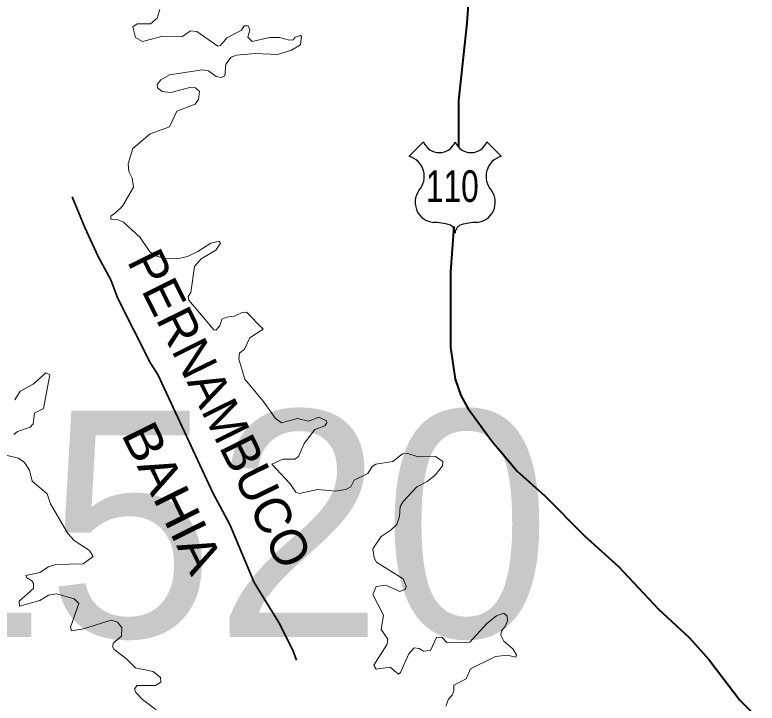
# Model space of a CAD drawing. Extents: x 553962 to 842807, y 8883888 to 9032388.
# Drawn here: x 579374 to 581014, y 8914801 to 8916321 of the extents above; entities that cross this region are included whole.
import ezdxf
from ezdxf.enums import TextEntityAlignment as Align

# ---------------------------------------------------------------- set-up
doc = ezdxf.new("R2010")
doc.units = 0
doc.header["$LTSCALE"] = 200
doc.linetypes.add('LONG_DASH_SHORT_DASH', pattern=[9.9, 6, -1.2, 1.5, -1.2])
doc.layers.add('6', color=7, linetype='Continuous', lineweight=13)

msp = doc.modelspace()

# ---------------------------------------------------------------- linework, layer by layer
at = {"layer": '6', "lineweight": 25}
for p, q in [((580244.9, 8916008.7), (580276.8, 8916040.7)), ((580416.7, 8916040.7), (580448.7, 8916008.7))]:
    msp.add_line(p, q, dxfattribs=at)
at = {"layer": '6', "lineweight": 40}
for points in [[(579213.9, 8917803.6), (579228.4, 8917763.4), (579242.2, 8917742.7), (579298.8, 8917690.5), (579364.6, 8917617.7), (579396.1, 8917591.3), (579545.7, 8917448.6), (579623.5, 8917387.3), (579718.5, 8917299.9), (579761.2, 8917250.1), (579934.8, 8917073.4), (579974.1, 8917041), (580094.4, 8916919), (580138.8, 8916860.8), (580185.2, 8916812.2), (580237.9, 8916747.8), (580356.4, 8916554.1), (580378.4, 8916492), (580386.2, 8916445.1), (580380.2, 8916408), (580372.4, 8916302.5), (580354.2, 8916132.1), (580354.2, 8916028.7)], [(580343.7, 8915853.7), (580336.1, 8915753.4), (580336.5, 8915587.3), (580346.4, 8915516.3), (580359, 8915480.1), (580374.6, 8915452.4), (580426, 8915381.5), (580483.5, 8915313.2), (580544.8, 8915258.9), (580632.4, 8915170.4), (580707.5, 8915102.2), (580796.1, 8915008), (580864.8, 8914944.9), (580908, 8914896.5), (580975.6, 8914807.3), (581014.1, 8914768.8)]]:
    msp.add_lwpolyline(points, dxfattribs=at)
at = {"layer": '6'}
for points in [[(580007.4, 8916273.3), (580005, 8916275.8), (579993.4, 8916271.9), (579988.7, 8916266.2), (579980.8, 8916265), (579958.6, 8916271.3), (579936.5, 8916271.3), (579898.3, 8916262), (579888.5, 8916271.8), (579893.2, 8916288), (579889.2, 8916296.8), (579880.4, 8916297.2), (579874.8, 8916287), (579841.8, 8916270.1), (579827.8, 8916253.1), (579822.2, 8916252.2), (579776.1, 8916284.1), (579776.1, 8916284.1), (579761.9, 8916285.8), (579744.5, 8916273.1), (579700.5, 8916273.9), (579656.1, 8916262.4), (579640, 8916271.3), (579634.5, 8916294.7), (579643.7, 8916301.5), (579673.1, 8916301.5), (579688.3, 8916313.8), (579694.3, 8916332.9)], [(579827, 8915819.2), (579826.3, 8915820.9), (579806.9, 8915817.1), (579778.4, 8915798), (579755.5, 8915787), (579732.5, 8915781.9), (579702, 8915783.2), (579689.3, 8915787), (579671.8, 8915797.6), (579650.6, 8915829.1), (579613.6, 8915863), (579601.7, 8915868.1), (579586, 8915869.9), (579586, 8915876.6), (579597.1, 8915884.3), (579611.5, 8915898.7), (579635.7, 8915940.4), (579632.8, 8915960), (579625.5, 8915975.2), (579623.8, 8915992.2), (579634.5, 8916026.2), (579673, 8916058.4), (579715.6, 8916073.8), (579731.3, 8916108.2), (579772.1, 8916123.5), (579779.7, 8916134.4), (579781.8, 8916151.9), (579772.9, 8916160), (579760.6, 8916160.9), (579718.1, 8916149.8), (579699.4, 8916151.6), (579689.2, 8916160), (579688, 8916167.1), (579696, 8916177.8), (579715.7, 8916188.6), (579788.6, 8916199.5), (579801.3, 8916197.8), (579818.4, 8916184.7), (579830.3, 8916182.6), (579837.5, 8916186.4), (579840.1, 8916212.3), (579852, 8916228), (579863.6, 8916232.3), (579905.1, 8916236.1), (579954.3, 8916233.9), (579985, 8916242.9), (580004.9, 8916254.8), (580007.4, 8916273.3)], [(579921.2, 8915628.2), (579885.3, 8915664.2), (579876.2, 8915663.8), (579859.2, 8915655.3), (579842.2, 8915653.6), (579830.8, 8915648.5), (579826.8, 8915634.3), (579817.6, 8915624.4), (579813.3, 8915625.1), (579758.5, 8915690.5), (579756.4, 8915699.1), (579762.7, 8915707.9), (579770.8, 8915765.3), (579785.7, 8915781.9), (579817.5, 8915801), (579828.2, 8915816.6), (579827, 8915819.2)], [(580319.7, 8915333.8), (580319.7, 8915334.1), (580303.4, 8915345.2), (580265, 8915344.8), (580242.4, 8915351.9), (580230.5, 8915351.1), (580209.3, 8915334.1), (580171.4, 8915328.2), (580163.5, 8915323.6), (580153.6, 8915308.2), (580123.4, 8915293.3), (580116.2, 8915278.5), (580104.8, 8915272.5), (580081.8, 8915268.7), (580043.5, 8915272.5), (580002, 8915263.6), (579994.3, 8915267), (579994.3, 8915267), (579982.4, 8915285.2), (579941.6, 8915328.6), (579966.2, 8915339.6), (579992.4, 8915339.6), (580000.2, 8915345.2), (580013.4, 8915374.5), (580036.8, 8915405.1), (580058.9, 8915413.2), (580063.1, 8915419.8), (580062.2, 8915424.6), (580045.2, 8915432.7), (580022.3, 8915423.4), (579998.1, 8915429.3), (579962.9, 8915419.5), (579949.7, 8915429.2), (579922.5, 8915467.5), (579881.7, 8915516.3), (579868.5, 8915560.6), (579869.8, 8915574.1), (579880.9, 8915582.8), (579893.2, 8915607.7), (579922.7, 8915626.6), (579921.2, 8915628.2)], [(579373.6, 8915470.5), (579385.1, 8915489.7), (579414.3, 8915505.3), (579442.3, 8915530.3), (579450.8, 8915526.1), (579436.8, 8915451.4), (579417.3, 8915441.1), (579414.3, 8915417.4), (579407.7, 8915410.3), (579379.6, 8915400.8), (579371.1, 8915394)], [(579340.4, 8915351.5), (579381.5, 8915341.8), (579394.8, 8915332.4), (579405.9, 8915314.9), (579411.8, 8915291.1), (579445.3, 8915262.8), (579445.3, 8915262.8), (579452.2, 8915240.7), (579490.9, 8915175.1), (579504.9, 8915159.9), (579538.8, 8915137.8), (579546.4, 8915124.3), (579524.3, 8915108.1), (579464, 8915106.8), (579448.3, 8915101.7), (579429.2, 8915089), (579398.2, 8915082.2), (579399.9, 8915077.5), (579411.4, 8915071.1), (579415.2, 8915065.2), (579415.2, 8915053.8), (579383.3, 8915026.2), (579384.2, 8915014.9)], [(580480.8, 8914902.8), (580482.1, 8914907.6), (580474.3, 8914920.3), (580454.4, 8914937.7), (580448, 8914950.4), (580448.9, 8914960.2), (580457.3, 8914969.6), (580462.4, 8914982.3), (580461.6, 8914992.9), (580454.3, 8914999.7), (580438.2, 8914993.8), (580417, 8914976.4), (580378.8, 8914935.2), (580328.7, 8914933.9), (580317.1, 8914946.6), (580305.5, 8914945.8), (580292, 8914916.9), (580276.5, 8914915.2), (580267, 8914921.1), (580255.9, 8914922.4), (580244.5, 8914909.3), (580225.8, 8914868.5), (580221.2, 8914864.7), (580202.9, 8914880.3), (580172.3, 8914875.7), (580167.2, 8914884.2), (580196.5, 8914930.9), (580198.2, 8914941.9), (580183.3, 8914963.2), (580188, 8914995), (580165.1, 8915040.5), (580171.9, 8915057.9), (580193.5, 8915060.9), (580224.5, 8915046.9), (580236.8, 8915052.4), (580238.5, 8915059.3), (580231.8, 8915074.9), (580173.1, 8915112.3), (580168, 8915121.3), (580164.7, 8915141.3), (580182.9, 8915168.8), (580205, 8915183.3), (580217.7, 8915195.6), (580223.7, 8915213), (580225.4, 8915235.1), (580231.8, 8915246.2), (580262.3, 8915278.4), (580284.9, 8915290), (580302.2, 8915303.9), (580318.7, 8915324.9), (580319.7, 8915333.8)], [(579384.2, 8915014.9), (579384.2, 8915014.7), (579429.2, 8915027.4), (579448, 8915038.8), (579465.7, 8915042.2), (579504.8, 8915030.8), (579515, 8915020.6), (579496.4, 8914968.3), (579498.8, 8914960.3), (579525.3, 8914964.9), (579586.4, 8914984), (579600.8, 8914979.4), (579609.8, 8914967.5), (579609.3, 8914948.3), (579591.5, 8914933.5), (579589.8, 8914925.9), (579593.2, 8914919.1), (579620.8, 8914897.8), (579640, 8914878.3), (579679.4, 8914870.2), (579695.2, 8914857.4), (579696, 8914847.2), (579684.5, 8914839.8), (579644.2, 8914839.6), (579637.8, 8914832.4), (579640.8, 8914823.8), (579655.7, 8914808.6), (579686.2, 8914786.1)], [(580326.1, 8914794.1), (580332, 8914809.3), (580340.1, 8914817.9), (580343.9, 8914827.7), (580343.5, 8914840), (580371.1, 8914854), (580380.9, 8914876.1), (580436.1, 8914903.3), (580461.9, 8914906.3), (580480.7, 8914902.3), (580480.8, 8914902.8)]]:
    msp.add_lwpolyline(points, dxfattribs=at)
at = {"layer": '6', "linetype": 'LONG_DASH_SHORT_DASH', "lineweight": 35}
msp.add_lwpolyline([(579500.5, 8915918.8), (579528, 8915851.1), (579557.9, 8915787.1), (579585.9, 8915736.1), (579601.5, 8915694.6), (579673.2, 8915551.9), (579689.7, 8915526.8), (579811.6, 8915263.9), (579848.4, 8915195.6), (579902.4, 8915066.8), (579956.9, 8914978.6), (579987.7, 8914917.9), (579996, 8914895.7)], dxfattribs=at)
at = {"layer": '6', "lineweight": 25}
for centre, radius, start, end in [((580311.8, 8916054.1), 37.4, 200.9593, 339.0407), ((580381.7, 8916054.1), 37.4, 200.9593, 339.0407), ((580232.4, 8915964.3), 46.1, 317.5721, 74.3689), ((580461.1, 8915964.3), 46.1, 105.6277, 222.4279), ((580303.1, 8915907.3), 44.9, 144.7373, 264.6578), ((580390.4, 8915907.3), 44.9, 275.3422, 35.2627), ((580298.8, 8915744.6), 118, 72.8937, 89.9006), ((580327.9, 8915839.3), 18.9, 357.6934, 72.9296), ((580365.7, 8915839.3), 18.9, 107.0704, 182.3065), ((580394.8, 8915744.6), 118, 90.0994, 107.1063)]:
    msp.add_arc(centre, radius, start, end, dxfattribs=at)

# ---------------------------------------------------------------- texts
at = {"layer": '6', "width": 0.75}
msp.add_text('110', height=70, dxfattribs=at).set_placement((580340.4, 8915907.8), align=Align.CENTER)
at = {"layer": '6'}
msp.add_text('PERNAMBUCO', height=80, rotation=296.367, dxfattribs=at).set_placement((579791, 8915433.4), align=Align.CENTER)
msp.add_text('MI-1520', height=500, dxfattribs=at).set_placement((578105.8, 8914946.5))
at = {"layer": '6', "width": 1.1}
msp.add_text('BAHIA', height=80, rotation=296.367, dxfattribs=at).set_placement((579686.1, 8915236.7), align=Align.CENTER)

doc.saveas('drawing.dxf')
